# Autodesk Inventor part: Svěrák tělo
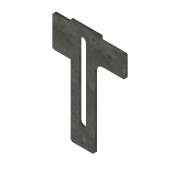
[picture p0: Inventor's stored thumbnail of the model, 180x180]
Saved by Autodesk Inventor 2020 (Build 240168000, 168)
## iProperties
Created: 2025-03
Part Number: Svěrák tělo
Material: Ocel
Document SubType Name: Modeling
Designer: doma
Density: 7.85 g/cm^3
Appearance: Plech
Mass: 4935.24 g
Surface Area: 1518.82 cm^2
Volume: 628.693 cm^3
Author: doma
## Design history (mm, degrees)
sketch "Náčrt1"
  geometry: L1 (4511.174, 517.318)-(4491.174, 517.318); L2 (4361.174, 517.318)-(4288.174, 517.318); L3 (4281.174, 510.318)-(4281.174, 384.318); L4 (4288.174, 377.318)-(4281.174, 384.318); L5 (4601.174, 424.318)-(4601.174, 510.318); L6 (4594.174, 417.318)-(4601.174, 424.318); L7 (4601.174, 510.318)-(4594.174, 517.318); L8 (4398.674, 472.318)-(4398.674, 206.12); L9 (4428.674, 472.318)-(4428.674, 206.12); L10 (4361.174, 367.318)-(4361.174, 74.318); L11 (4368.174, 67.318)-(4361.174, 74.318); L12 (4398.674, 162.318)-(4398.674, 206.12); L13 (4428.674, 206.12)-(4428.674, 162.318); L14 (4466.174, 377.318)-(4466.174, 74.318); L15 (4459.174, 67.318)-(4466.174, 74.318); L16 (4361.174, 377.318)-(4288.174, 377.318); L17 (4361.174, 377.318)-(4361.174, 367.318); L18 (4361.174, 517.318)-(4361.174, 529.318); L19 (4361.174, 529.318)-(4491.174, 529.318); L20 (4491.174, 529.318)-(4491.174, 517.318); L21 (4368.174, 67.318)-(4459.174, 67.318); L22 (4511.174, 517.318)-(4594.174, 517.318); L23 (4594.174, 417.318)-(4511.174, 417.318); L24 (4506.174, 417.318)-(4511.174, 417.318); L25 (4281.174, 510.318)-(4288.174, 517.318); A1 r 15 centre (4413.674, 472.318) between (4428.674, 472.318) and (4398.674, 472.318); A2 r 15 centre (4413.674, 162.318) between (4398.674, 162.318) and (4428.674, 162.318); A3 r 40 centre (4506.174, 377.318) between (4506.174, 417.318) and (4466.174, 377.318); 28 further points
  constraints: 50 end point, 6 point on circle, 3 centre point
extrude "Vysunutí1" new body sketch "Náčrt1" distance "d54" = 10; taper "d55" = 0 deg
sketch "Náčrt2"
  geometry: L1 (4420.706, 152.318)-(4473.643, 152.318); L2 (4368.174, 67.318)-(4459.174, 67.318) reference; L3 (4413.674, 67.318)-(4413.674, 212.467); L4 (4380.174, 92.318)-(4380.174, 251.506); L5 (4447.174, 92.318)-(4447.174, 247.17); 6 further points
  constraints: 8 end point, 3 point on line, 3 symmetric about line, 3 vertical, 2 midpoint, 1 horizontal
  dimensions: "d56" = 25 distance from line of L2 L5.start; "d57" = 60 distance of point (4447.174, 152.318) point (4447.174, 212.318); "d73" = 60 distance of L5.start point (4447.174, 152.318); "d85" = 20 distance from line of L2 point (4413.674, 87.318); "d86" = 33.5 distance between parallel lines of L3 L5
hole "Díra1" sketch "Náčrt2" diameter "d58" = 6.647; stored, may be unused: countersink angle "d62" = 90 deg, drill point angle "d64" = 118 deg; dims "d59" = 16, "d60" = 9, "d61" = 5, "d63" = 22.2
hole "Díra2" sketch "Náčrt2" diameter "d65" = 10; stored, may be unused: countersink angle "d69" = 90 deg, drill point angle "d71" = 118 deg; dims "d66" = 10, "d67" = 9, "d68" = 5, "d70" = 14.2
sketch "Náčrt3"
  geometry: L1 (4601.174, 424.318)-(4601.174, 510.318) reference; L2 (4594.174, 517.318)-(4491.174, 517.318) reference; A1 r 50 centre (4511.174, 517.318) between (4558.871, 502.318) and (4532.969, 472.318); 3 further points
  constraints: 4 point on circle, 1 centre point, 1 point on line
  dimensions: "d74" = 100 diameter of A1; "d75" = 90 distance from line of L1 A1.centre; "d76" = 15 distance from line of L2 A1.start; "d77" = 45 distance from line of A1.end L2
hole "Díra3" sketch "Náčrt3" at (4558.871, 502.318), (4532.969, 472.318), (4463.478, 502.318), (4489.38, 472.318) diameter "d78" = 9; stored, may be unused: countersink angle "d82" = 90 deg, drill point angle "d84" = 118 deg; dims "d79" = 16, "d80" = 14, "d81" = 8, "d83" = 8
chamfer "Zkosení1" distance "d87" = 3; stored, may be unused: second distance "d88" = 2, angle "d89" = 45 deg
chamfer "Zkosení2" distance "d90" = 5; stored, may be unused: second distance "d91" = 2, angle "d92" = 45 deg
node "Těleso1"
